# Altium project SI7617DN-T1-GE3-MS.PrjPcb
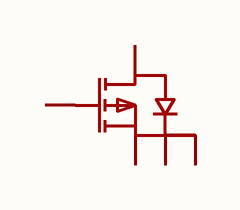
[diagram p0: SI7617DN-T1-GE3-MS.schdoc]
1 sheet, 1 parts. Net scope: global (net labels, ports and power ports of the same name join across sheets).

## Sheet SI7617DN-T1-GE3-MS.schdoc
size 127 x 101 mm

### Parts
Q?  si7617dn-t1-ge3-ms  [PDFN3333-8_L3.1-W3.2-P0.65-LS3.4-BL_1]  (value not drawn)

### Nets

Not connected (* = marked no-connect by the designer): Q? 1(S) 2(S) 3(S) 4(G) 5(D)

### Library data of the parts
Q? = si7617dn-t1-ge3-ms: 数量:1个P沟道;漏源电压(Vdss):30V;连续漏极电流(Id):50A;导通电阻(RDS(on)):9mΩ@-10V;耗散功率(Pd):37W;阈值电压(Vgs(th)):1.2V;; Manufacturer: MSKSEMI(美森科); AddInBom: yes; ModelId: c288237aeb774e1d92142cc9eea176d4; ModelTransform: 118.8974,118.8974,0,90,0,0,0,19.486,0; Number: 1个P沟道; Drain to Source Voltage: 30V; Current - Continuous Drain(Id): 50A; Pd - Power Dissipation: 37W; Gate Threshold Voltage (Vgs(th)): 1.2V; Gate Charge(Qg): 22nC; Input Capacitance(Ciss): 2.215nF; Reverse Transfer Capacitance (Crss@Vds): 237pF; Type: P沟道; Output Capacitance(Coss): 310pF; Vgs: ±20V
